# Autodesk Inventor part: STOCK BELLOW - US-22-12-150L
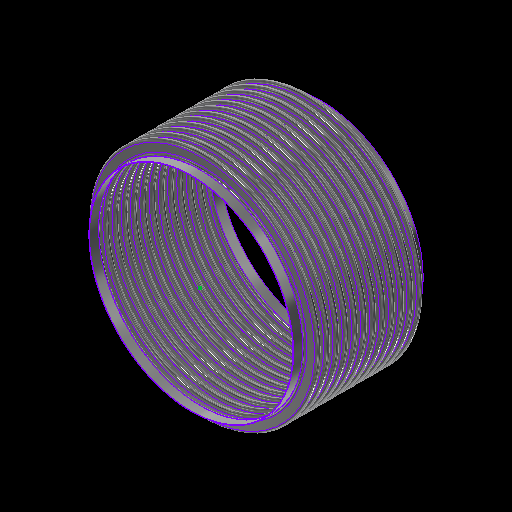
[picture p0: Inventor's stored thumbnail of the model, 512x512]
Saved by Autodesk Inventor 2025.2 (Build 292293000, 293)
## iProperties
Category: 16 GA (0.060 THICK)
RuleStatus: InUse
Created: 2024-01
Part Number: STOCK BELLOW - US-22-12-150L
Project: =STOCK BELLOWS: <Stock Number><SFILL>
Material: ASTM A240-304
Description: =STOCK BELLOWS: <Stock Number>, <SID_> I.D., <SOD_> O.D., <SPLY_> PLY, <Category>, <SNET_CONS> CONS.<PITCH_><STANGENT_> TANGENT<SFILL>
Document SubType Name: Sheet Metal
Designer: GS
Stock Number: U.S-22-12-150L
Surface Area: 38344.1 cm^2
Volume: 2909.56 cm^3
Sheet Metal Rule: Default
Appearance: STAINLESS STEEL
Mass: 23443.1 g
Density: 8.05729 g/cm^3
THK: 0.036
ID: 3.500
OD: 4.250
CONS_: 2
PITCH: 0.500
TANGENT: 0.500
BELLOWS_UPSET: 0.000
d79: 1.000
d82: 1.000
d83: 26.000
d84: 24.000
d174: 8
d214: 8
STHK_: 0.060
SID_: 22.000
SOD_: 24.750
SPITCH_: 1.000
STANGENT__: 1.000
SBELLOWS_UPSET_: 0.000
SDIFF_TAN: 1.000
d252: 2
d275: 2
d287: 0.050
d289: 0.500
d290: 0.000
SOD_NECK: 22 1/8
PLY: 1
PSET: 4.178
PBAR: 1.035
COUNTER: 1.500
NET_TUBE: 3.071
CONS: 2
S_CONS: 0
NET_CONS: 2
ID_M: 88.90 mm
OD_M: 107.95 mm
THK_M: 0.91 mm
ID_U: 3.500 in
OD_U: 4.250 in
THK_U: 0.036 in
TANGENT2: 0.500
TAN_TO_TAN: 1.000 in
d80: 2.571
d81: 10
SID: 2.375
SCONS_: 12
SPITCH: 0.250
STANGENT_: 1.000
SBELLOWS_UPSET: 0.000
SNET_CONS: 12
SS_CONS: 0
SCONS: 8
d190: 8
d191: 1
d192: 1
d193: 8
d194: 0
SIZE: 22.00
PRESSURE: 150
d230: 8
STANGENT: 4.000
SPLY_: 1
d233: 8
d234: 0
d263: 2
d265: 1
d268: 2
d269: 0
d286: 2
d288: 1
d291: 2
d292: 0
SREROLL: 0.750
BLETP: 1.000 ul
PRES_Copy: 85
MATTABLE: 20 GA (0.036 THICK)
PART_NUMBER: U.S-22-12-150L
PITCH_: =, <SPITCH_> PITCH,
CFILL: .
SFILL: .
MESH: ,
COMP: 2.23
EXT: 1.12
LAT: 0.38
ANG: 573
ASR: 2755
LSR: 15678
ANSR: 5052
PRES: 150
COMPM: 22.3
EXTM: 11.15
LATM: 3.80
ASRM: 482.483
PRESM: 10.342
LSRM: 2745.688
ANSRM: 884.757
TEMPMIN: 20
TEMPMAX: 800
TEMPMINM: -7
TEMPMAXM: 427
WEIGHTM: 23.443
WEIGHT: 51.683
Author: GS
Keywords: 20 GA (0.036 THICK)
Comments: =STOCK BELLOW - <STOCK NUMBER>
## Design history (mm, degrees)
sketch "Sketch2"
  geometry: L1 (0, -177.245)-(0, 562.856) reference; L2 (45.364, 0)-(44.45, 0); L3 (48.082, -2.718)-(50.343, -2.718); L4 (48.082, -3.632)-(50.343, -3.632); L5 (50.343, -9.982)-(48.082, -9.982); L6 (50.343, -9.068)-(48.082, -9.068); L7 (45.364, -12.7)-(44.45, -12.7); L8 (48.082, 0)-(48.082, -12.7); L9 (50.343, -6.35)-(53.975, -6.35); L10 (44.45, 0)-(44.45, -12.7); L11 (20.376, 102.841)-(20.376, 101.926); L12 (58.262, 457.127)-(58.262, 349.177); L13 (58.262, 444.427)-(58.262, 336.477); L14 (93.133, -58.817)-(93.133, -71.517); L15 (118.746, -66.401)-(118.746, -66.401); L16 (50.343, -9.068)-(50.343, -9.982); L17 (48.082, -9.068)-(48.082, -9.982); L18 (48.082, -9.525)-(50.343, -9.525); L19 (53.975, 0)-(53.975, -12.7); L20 (-50.343, -9.068)-(-50.343, -9.982); L21 (-50.343, -2.718)-(-48.082, -2.718); L22 (-50.343, -3.632)-(-48.082, -3.632); L23 (-48.082, -9.068)-(-50.343, -9.068); L24 (-50.343, -9.525)-(-48.082, -9.525); L25 (-48.082, -9.982)-(-50.343, -9.982); L26 (-48.082, -9.068)-(-48.082, -9.982); L27 (-44.45, 0.653)-(-44.45, -12.047); L28 (-48.082, -6.35)-(-44.45, -6.35); L29 (-50.343, 0.653)-(-50.343, -12.7); L30 (-53.061, 0)-(-53.975, 0); L31 (-53.975, 0)-(-53.975, -12.7); L32 (-53.061, -12.7)-(-53.975, -12.7); A1 r 2.718 centre (48.082, 0) between (45.364, 0) and (48.082, -2.718); A2 r 3.632 centre (48.082, 0) between (44.45, 0) and (48.082, -3.632); A3 r 3.632 centre (50.343, -6.35) between (50.343, -9.982) and (50.343, -2.718); A4 r 2.718 centre (50.343, -6.35) between (50.343, -9.068) and (50.343, -3.632); A5 r 2.718 centre (48.082, -12.7) between (48.082, -9.982) and (45.364, -12.7); A6 r 3.632 centre (48.082, -12.7) between (48.082, -9.068) and (44.45, -12.7); A7 r 3.175 centre (50.343, -6.35) between (50.343, -9.525) and (53.518, -6.35); A8 r 3.175 centre (48.082, -12.7) between (48.082, -9.525) and (44.907, -12.7); A9 r 2.718 centre (-50.343, -12.7) between (-50.343, -9.982) and (-53.061, -12.7); A10 r 2.718 centre (-48.082, -6.35) between (-48.082, -9.068) and (-48.082, -3.632); A11 r 3.175 centre (-48.082, -6.35) between (-48.082, -9.525) and (-44.907, -6.35); A12 r 3.632 centre (-48.082, -6.35) between (-48.082, -9.982) and (-48.082, -2.718); A13 r 3.175 centre (-50.343, -12.7) between (-50.343, -9.525) and (-53.518, -12.7); A14 r 3.632 centre (-50.343, -12.7) between (-50.343, -9.068) and (-53.975, -12.7); A15 r 2.718 centre (-50.343, 0) between (-53.061, 0) and (-50.343, -2.718); A16 r 3.632 centre (-50.343, 0) between (-53.975, 0) and (-50.343, -3.632); 10 further points
  constraints: 62 end point, 38 point on circle, 20 tangent, 16 centre point, 12 parallel, 9 midpoint, 7 vertical, 6 coincident, 6 concentric, 6 point on line, 4 equal radius, 4 perpendicular, 3 horizontal, 1 collinear, 1 horizontal alignment, 10 other
  dimensions: "THK" = 0.9144 distance of L11.start L11.end; "ID" = 88.9 distance of L11.end point (20.376, 13.026); "OD" = 107.95 distance of L12.start L12.end; "PITCH" = 12.7 distance of L12.start L13.start; "TANGENT" = 12.7 distance of L14.start L14.end; "BELLOWS_UPSET" = 0 distance of L15.start L15.end; "d43" = 88.9 diameter of L10 L1 (= ID); "d44" = 107.95 diameter of L9.end L1 (= OD); "d45" = 0.9144 distance between parallel lines of L5 L6 (computed from THK, PLY); "d46" = 3.6322 radius of A3 (computed from PITCH, THK, PLY); "UPSET_PITCH" = 12.7 distance of L2.end L7.end (derived); "SIDEWALL_ANGLE" = 360 deg dimension on L3 L9 (derived); "CON_GAP" = 5.4356 distance of point (48.082, -9.068) point (48.082, -3.632) (derived); "TAN1" = 4.98728 dimension on A8 (derived); "TAN2" = 4.98728 dimension on A7 (derived); "LEG1" = 2.2606 distance of L18.start L18.end (derived); "d278" = 0.9144 distance between parallel lines of L25 L23 (derived); "d279" = 3.6322 radius of A12 (derived); "d280" = 12.7 distance of L30.end L31.end (derived); "d281" = 360 deg dimension on L21 L28 (derived); "d282" = 5.4356 distance of point (-50.343, -9.068) point (-50.343, -3.632) (derived); "d283" = 4.98728 dimension on A13 (derived); "d284" = 4.98728 dimension on A11 (derived); "d285" = 2.2606 distance of L24.start L24.end (derived); "d293" = 88.9 diameter of L27 L1 (derived); "d294" = 107.95 diameter of L31 L1 (derived)
  node "Sketch Rectangular Pattern1" dims "d31" = 25.4, "ID" = 88.9
  node "Sketch Rectangular Pattern2" dims "d39" = 25.4, "PITCH" = 12.7
revolve "CONS" stored, may be unused: angle "d48" = 90 deg
node "BELLOW MIDPLANE"
pattern_linear "Rectangular Pattern2" dims "d52" = 12.7 (= UPSET_PITCH)
sketch "Sketch5"
  geometry: C1 r 45.364 at (0, 0) reference; C2 r 44.45 at (0, 0) reference
extrude "TANGENT" new body sketch "Sketch5" distance "d53" = 12.7 (= TANGENT); taper "d54" = 0 deg
revolve "SAMETAN" stored, may be unused: angle "d65" = 90 deg
revolve "DIFFTAN" stored, may be unused: angle "d70" = 90 deg
sketch "Sketch9"
  geometry: L1 (53.319, 0)-(-53.319, 0) reference; L2 (0, -17.78)-(0, 17.78) reference; L3 (38.085, 0)-(-38.085, 0); L4 (38.085, -11.906)-(38.085, 11.906); L5 (25.385, -11.906)-(25.385, 11.906); L6 (13.15, 11.906)-(13.15, -11.906); L7 (-25.385, -11.906)-(-25.385, 11.906); L8 (-38.085, -11.906)-(-38.085, 11.906); L9 (37.291, -11.906)-(37.291, 11.906); L10 (38.085, -11.906)-(37.291, -11.906); L11 (38.085, 11.906)-(37.291, 11.906); L12 (13.546, 11.906)-(12.753, 11.906); L13 (12.753, 11.906)-(12.753, -11.906); L14 (12.753, -11.906)-(13.546, -11.906); L15 (13.546, -11.906)-(13.546, 11.906); L16 (-13.546, 11.906)-(-13.546, -11.906); L17 (-13.15, 11.906)-(-13.15, -11.906); L18 (-13.546, -11.906)-(-12.753, -11.906); L19 (-12.753, -11.906)-(-12.753, 11.906); L20 (-12.753, 11.906)-(-13.546, 11.906); L21 (-38.085, -11.906)-(-37.291, -11.906); L22 (-37.291, -11.906)-(-37.291, 11.906); L23 (-37.291, 11.906)-(-38.085, 11.906); L24 (-38.085, 11.906)-(-38.085, -11.906); L25 (38.085, -0.397)-(-38.085, -0.397); L26 (-38.085, -0.397)-(-38.085, 0.397); L27 (-38.085, 0.397)-(38.085, 0.397); L28 (38.085, 0.397)-(38.085, -0.397); L29 (-38.085, 11.906)-(38.085, 11.906); L30 (38.085, 11.906)-(38.085, 12.7); L31 (38.085, 12.7)-(-38.085, 12.7); L32 (-38.085, 12.7)-(-38.085, 11.906); L33 (38.085, -11.906)-(-38.085, -11.906); L34 (-38.085, -11.906)-(-38.085, -12.7); L35 (-38.085, -12.7)-(38.085, -12.7); L36 (38.085, -12.7)-(38.085, -11.906); 30 further points
  constraints: 68 end point, 13 midpoint, 13 parallel, 8 horizontal, 7 perpendicular, 6 equal length, 3 point on line, 2 vertical, 14 other
  dimensions: "d115" = 23.8125 distance of L4.start L4.end (derived); "d116" = 12.7 distance between parallel lines of L4 L5 (derived); "d117" = 12.23516 distance between parallel lines of L5 L6 (derived); "d125" = 38.53427 distance between parallel lines of L7 L6 (derived); "d127" = 12.7 distance between parallel lines of L8 L7 (derived); "d128" = 24.93516 distance between parallel lines of L6 L4 (derived); "d130" = 76.16943 distance between parallel lines of L8 L4 (derived); "RULER_THK" = 0.79375 distance between parallel lines of L4 L9; "d135" = 0.79375 distance of L13.end L14.end (derived); "d138" = 26.29911 distance of L13.end L16.end (derived); "d143" = 0.79375 distance of L22.end L8.end (derived); "d144" = 0.79375 distance between parallel lines of L27 L25 (derived)
extrude "RULER" join sketch "Sketch9" distance "d149" = 0.79375 (derived); taper "d150" = 0 deg
extrude "BARS" join sketch "Sketch9" distance "d151" = 0.79375 (derived); taper "d152" = 0 deg
pattern_linear "Rectangular Pattern4" dims "d155" = 26.29911 (derived)
sketch "Sketch13"
  geometry: L1 (93.149, -52.467)-(93.149, -77.867); L2 (280.924, 0)-(279.4, 0); L3 (280.924, -25.4)-(279.4, -25.4); L4 (307.213, -19.812)-(286.512, -19.812); L5 (307.213, -18.288)-(286.512, -18.288); L6 (307.213, -12.7)-(314.325, -12.7); L7 (286.512, -5.588)-(307.213, -5.588); L8 (286.512, 0)-(286.512, -25.4); L9 (279.4, 0)-(279.4, -25.4); L10 (58.254, 132.219)-(58.254, -496.431); L11 (58.254, 106.819)-(58.254, -521.831); L12 (58.254, 56.019)-(58.254, -572.631); L13 (58.254, 30.619)-(58.254, -598.031); L14 (58.254, 5.219)-(58.254, -623.431); L15 (58.254, -20.181)-(58.254, -648.831); L16 (58.254, -45.581)-(58.254, -674.231); L17 (58.254, 81.419)-(58.254, -547.231); L18 (20.376, 103.45)-(20.376, 101.926); L19 (286.512, -7.112)-(307.213, -7.112); L20 (0, -835.521)-(0, 293.509) reference; L21 (-62.865, 0)-(377.19, 0) reference; A1 r 5.588 centre (286.512, 0) between (280.924, 0) and (286.512, -5.588); A2 r 5.588 centre (286.512, -25.4) between (286.512, -19.812) and (280.924, -25.4); A3 r 7.112 centre (286.512, -25.4) between (286.512, -18.288) and (279.4, -25.4); A4 r 5.588 centre (307.213, -12.7) between (307.213, -18.288) and (307.213, -7.112); A5 r 7.112 centre (307.213, -12.7) between (307.213, -19.812) and (307.213, -5.588); A6 r 7.112 centre (286.512, 0) between (279.4, 0) and (286.512, -7.112); 6 further points; 1 other entity
  constraints: 38 end point, 15 point on circle, 9 tangent, 6 centre point, 6 parallel, 5 vertical alignment, 4 point on line, 4 vertical, 3 coincident, 3 concentric, 2 collinear, 2 equal radius, 1 horizontal, 1 perpendicular, 23 other
  dimensions: "SBELLOWS_UPSET_" = 0 distance of point (118.762, -66.401) point (118.762, -66.401); "STOTAL_THK_BELLOW__" = 1.524 distance between parallel lines of L4 L5 (derived); "d224" = 7.112 radius of A5 (derived); "d225" = 25.4 distance of L2.end L3.end (derived); "SSIDEWALL_ANGLE_" = 0 deg angle of L7 L6 (derived); "SSCON_GAP_" = 11.176 distance of point (286.512, -18.288) point (286.512, -7.112) (derived); "d235" = 558.8 diameter of L9 L20 (derived); "d236" = 628.65 diameter of L6.end L20 (derived)
  node "Sketch Rectangular Pattern4" dims "d228" = 25.4
  node "Sketch Rectangular Pattern5" dims "d229" = 25.4
revolve "SBELLOW" stored, may be unused: angle "d197" = 90 deg
pattern_linear "Rectangular Pattern5" dims "d204" = 25.4 (derived)
revolve "STANGENT" stored, may be unused: angle "d240" = 90 deg
revolve "SSAMETAN" stored, may be unused: angle "d241" = 90 deg
revolve "SDIFFTAN" stored, may be unused: angle "d246" = 90 deg
revolve "INVCON" stored, may be unused: angle "d295" = 90 deg
pattern_linear "Rectangular Pattern6" dims "d298" = 12.7 (derived)
revolve "INVTANGENT" stored, may be unused: angle "d302" = 90 deg
revolve "INVSAMETAN" stored, may be unused: angle "d307" = 90 deg
revolve "INVDIFFTAN" stored, may be unused: angle "d312" = 90 deg
sketch "ID BELLOW MOUNT CALC"
  geometry: L1 (44.45, 0)-(38.1, 0); L2 (38.1, 0)-(38.1, 12.7); L3 (38.1, 12.7)-(44.45, 12.7); L4 (44.45, 12.7)-(44.45, 0); L5 (36.513, 12.7)-(35.598, 12.7); L6 (35.598, 12.7)-(35.598, 0); L7 (35.598, 0)-(36.513, 0); L8 (36.513, 0)-(36.513, 12.7); L9 (0, -2.54)-(0, 15.24) reference; L10 (-8.89, 0)-(53.34, 0) reference; 1 further point
  constraints: 16 end point, 5 parallel, 2 collinear, 2 horizontal, 2 perpendicular
  dimensions: "d314" = 12.7 distance of L5.end L6.end (derived); "d315" = 0.9144 distance of L5.start L5.end (derived); "IG" = 1.5875 distance between parallel lines of L2 L8; "PIPE_OD" = 88.9 diameter of L4 L9; "PIPE_WALL" = 6.35 distance of L2.end L3.end; "ID_MT_BELLOW" = 71.1962 diameter of L6 L9 (derived)
revolve "CFILL" stored, may be unused: angle "d320" = 90 deg
pattern_linear "Rectangular Pattern7" dims "d323" = 12.7 (derived)
revolve "SFILL" stored, may be unused: angle "d324" = 90 deg
pattern_linear "Rectangular Pattern8" dims "d327" = 25.4 (derived)
node "STOCK BELLOW MIDPLANE"
node "BELLOW"
sketch "Sketch6"
  geometry: L1 (-12.7, 45.364)-(0, 45.364); L2 (0, 45.364)-(0, 44.45); L3 (0, 44.45)-(-12.7, 44.45); L4 (-12.7, 44.45)-(-12.7, 45.364); L5 (10.16, 0)-(-60.96, 0) reference; L6 (-38.1, -89.422)-(-38.1, 153.44) reference; 1 further point
  constraints: 8 end point, 2 parallel, 1 horizontal, 1 perpendicular
  dimensions: "d61" = 12.7 distance of L2.end L3.end (derived); "d62" = 0.9144 distance of L1.end L2.end (derived); "d63" = 88.9 diameter of L3 L5 (derived); "d64" = 25.4 distance between parallel lines of L4 L6 (derived)
sketch "Sketch12"
  geometry: 1 further point
sketch "Sketch14"
  geometry: L1 (-25.4, 280.924)-(0, 280.924); L2 (0, 280.924)-(0, 279.4); L3 (0, 279.4)-(-25.4, 279.4); L4 (-25.4, 279.4)-(-25.4, 280.924); L5 (5.08, 0)-(-30.48, 0) reference; L6 (0, -56.185)-(0, 337.109) reference; 1 further point
  constraints: 8 end point, 2 parallel, 1 collinear, 1 horizontal, 1 perpendicular
  dimensions: "d237" = 1.524 distance of L3.end L1.start (derived); "d238" = 558.8 diameter of L3 L5 (derived); "d239" = 25.4 distance of L1.start L1.end (derived); "SOD_NECK" = 561.848 diameter of L1 L5 (derived)
sketch "Sketch15"
  geometry: L1 (-56.185, 0)-(337.109, 0) reference; L2 (279.4, -304.8)-(280.924, -304.8); L3 (280.924, -304.8)-(280.924, -330.2); L4 (280.924, -330.2)-(279.4, -330.2); L5 (279.4, -330.2)-(279.4, -304.8); L6 (0, -398.78)-(0, 81.28) reference; 1 further point
  constraints: 8 end point, 2 parallel, 1 horizontal, 1 perpendicular
  dimensions: "d205" = 25.4 distance of L4.end L2.start (derived); "d206" = 1.524 distance of L3.end L4.end (derived); "d207" = 558.8 diameter of L5 L6 (derived); "d208" = 304.8 distance between parallel lines of L1 L2 (derived)
node "TANGENT_"
node "SAME_TAN"
sketch "Sketch8"
  geometry: L1 (45.364, -25.4)-(44.45, -25.4); L2 (44.45, -25.4)-(44.45, -38.1); L3 (44.45, -38.1)-(45.364, -38.1); L4 (45.364, -38.1)-(45.364, -25.4); L5 (0, -48.26)-(0, 22.86) reference; L6 (-89.422, 0)-(153.44, 0) reference; 1 further point
  constraints: 8 end point, 2 parallel, 1 horizontal, 1 perpendicular
  dimensions: "d66" = 88.9 diameter of L2 L5 (derived); "TOTAL_THK_BELLOW" = 0.9144 distance of L2.end L3.end (derived); "d68" = 25.4 distance between parallel lines of L1 L6 (derived); "d69" = 12.7 distance of L1.end L2.end (derived)
node "DIFF_TAN"
node "Sketch Rectangular Pattern3" dims "d138" = 26.29911 (derived), "d141" = 25.4
node "SBELLOW_"
node "STANGENT_"
node "SSAME_TAN"
sketch "Sketch16"
  geometry: L1 (280.924, -304.8)-(279.4, -304.8); L2 (279.4, -304.8)-(279.4, -330.2); L3 (279.4, -330.2)-(280.924, -330.2); L4 (280.924, -330.2)-(280.924, -304.8); L5 (0, -398.78)-(0, 81.28) reference; L6 (-56.185, 0)-(337.109, 0) reference; 1 further point
  constraints: 8 end point, 2 parallel, 1 horizontal, 1 perpendicular
  dimensions: "SDIFF_TAN" = 25.4 distance of L3.end L1.start; "d243" = 1.524 distance of L2.end L3.end (derived); "d244" = 304.8 distance between parallel lines of L1 L6 (derived); "d245" = 558.8 diameter of L2 L5 (derived)
node "SDIFF_TAN"
body "Solid15"
sketch "Sketch17"
  geometry: L1 (53.975, 12.7)-(53.061, 12.7); L2 (53.061, 12.7)-(53.061, 0); L3 (53.061, 0)-(53.975, 0); L4 (53.975, 0)-(53.975, 12.7); L5 (0, -2.54)-(0, 15.24) reference; L6 (-10.795, 0)-(64.77, 0) reference; 2 further points
  constraints: 8 end point, 2 parallel, 1 horizontal, 1 midpoint, 1 perpendicular, 1 point on line
  dimensions: "INVTANGENT" = 12.7 distance of L3.end L1.start (derived); "d300" = 0.9144 distance of L1.start L1.end (derived); "d301" = 107.95 diameter of L4 L5 (derived)
body "Solid16"
sketch "Sketch18"
  geometry: L1 (53.975, -25.4)-(53.061, -25.4); L2 (53.061, -25.4)-(53.061, -38.1); L3 (53.061, -38.1)-(53.975, -38.1); L4 (53.975, -38.1)-(53.975, -25.4); L5 (-10.795, 0)-(64.77, 0) reference; L6 (0, -48.26)-(0, 22.86) reference; 1 further point
  constraints: 8 end point, 2 parallel, 1 horizontal, 1 perpendicular
  dimensions: "d303" = 25.4 distance between parallel lines of L1 L5 (derived); "d304" = 12.7 distance of L3.end L1.start (derived); "d305" = 0.9144 distance of L2.end L3.end (derived); "d306" = 107.95 diameter of L4 L6 (derived)
body "Solid17"
sketch "Sketch19"
  geometry: L1 (53.975, -25.4)-(53.061, -25.4); L2 (53.061, -25.4)-(53.061, -38.1); L3 (53.061, -38.1)-(53.975, -38.1); L4 (53.975, -38.1)-(53.975, -25.4); L5 (0, -48.26)-(0, 22.86) reference; L6 (-10.795, 0)-(64.77, 0) reference; 1 further point
  constraints: 8 end point, 2 parallel, 1 horizontal, 1 perpendicular
  dimensions: "d308" = 12.7 distance of L1.end L2.end (derived); "d309" = 107.95 diameter of L4 L5 (derived); "d310" = 0.9144 distance of L2.end L3.end (derived); "d311" = 25.4 distance between parallel lines of L1 L6 (derived)
body "Solid18"
body "Solid19"
body "Solid20"
other parameters: "BMPL" = -152.4, "PSET" = 106.1212 (computed from OD, THK, PLY) [user parameter], "PBAR" = 26.29911 (= 0.570796 x PITCH + OD - ID) [user parameter; used in 1 equation term], "COUNTER" = 15 [user parameter], "NET_TUBE" = 77.99823 (computed from CONS_, PBAR, TANGENT) [user parameter], "S_CONS" = 0 [user parameter; used in 1 equation term], "ID_M" = 88.9 (= ID) [user parameter], "OD_M" = 107.95 (= OD) [user parameter], "THK_M" = 0.9144 (= THK) [user parameter], "ID_U" = 88.9 (= ID) [user parameter], "OD_U" = 107.95 (= OD) [user parameter], "THK_U" = 0.9144 (= THK) [user parameter], "D_UNITS" = 0 [user parameter], "TANGENT2" = 12.7 [user parameter], "TAN_TO_TAN" = 25.4 [user parameter], "OD_NECK" = 90.7288 [user parameter], "d79" = 25.4, "d80" = 65.29823 [user parameter], "d82" = 25.4, "d83" = 660.4, "d84" = 609.6, "sa_0" = 4, "FRAME_THK" = 0.79375 [user parameter], "CON_FLAT" = 12.23516 [user parameter], "SID" = 60.325 [user parameter], "SPITCH" = 6.35 [user parameter], "STANGENT_" = 25.4 [user parameter], "SBELLOWS_UPSET" = 0 [user parameter], "SS_CONS" = 0 [user parameter], "STAN_TO_TAN_" = 304.8 [user parameter], "d100" = 1.524 [user parameter], "d191" = 25.4 [user parameter], "d194" = 0 [user parameter], "STANGENT" = 101.6 [user parameter], "d234" = 0 [user parameter], "SUPSET_PITCH_" = 25.4 [user parameter], "d269" = 0 [user parameter], "d287" = 1.27, "d289" = 12.7, "d290" = 0, "d292" = 0 [user parameter], "Thickness" = 3.048 (derived), "KFactor" = 4.4, "BendRadius" = 3.048 (derived), "BendReliefWidth" = 3.048 (derived), "BendReliefDepth" = 1.524 (derived), "CornerReliefSize" = 12.192 (derived), "SeamGap" = 0.00508, "MinimumRemnant" = 6.096 (derived), "TransitionRadius" = 3.048 (derived), "JacobiRadiusSize" = 3.048 (derived), "GapSize" = 3.048 (derived), "SREROLL" = 19.05 [user parameter], "CUR_STK_PITCH" = 25.4 [user parameter], "d328" = -152.4 (derived), "ASR" = 27550 [user parameter], "LSR" = 156780 [user parameter], "ANSR" = 50520 [user parameter], "BLETP" = 1 [user parameter], "ASRM" = 4824.8315 [user parameter], "PRESM" = 103.41975 [user parameter], "LSRM" = 27456.8814 [user parameter], "ANSRM" = 8847.5676 [user parameter], "TEMPMIN" = 2664.83333 [user parameter], "TEMPMAX" = 6998.16667 [user parameter], "TEMPMINM" = 2664.83333 [user parameter], "TEMPMAXM" = 6998.16667 [user parameter], "WEIGHT" = 234.43146 [user parameter], "WEIGHTM" = 0.23443 [user parameter]
